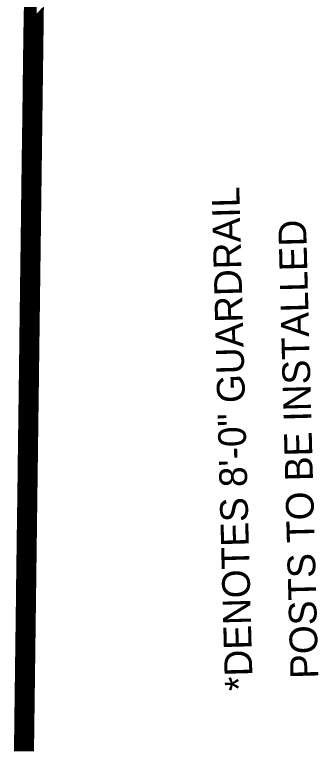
# Model space of a CAD drawing. Extents: x 1929624 to 1936506, y 596315 to 605721.
# Drawn here: x 1932362.2 to 1932427.8, y 600451.3 to 600610.8 of the extents above; entities that cross this region are included whole.
import ezdxf

# ---------------------------------------------------------------- set-up
doc = ezdxf.new("R2010")
doc.units = 0
doc.layers.add('Default', color=7, linetype='Continuous')

msp = doc.modelspace()

# ---------------------------------------------------------------- linework, layer by layer
at = {"layer": 'Default'}
for p, q in [((1932365.29, 600687.8), (1932362.18, 600451.38)), ((1932369.13, 600675.3), (1932366.19, 600451.33)), ((1932365.09, 600672.7), (1932366.76, 600610.75)), ((1932365.08, 600671.45), (1932366.71, 600610.69)), ((1932365.06, 600670.2), (1932366.66, 600610.64)), ((1932365.03, 600667.7), (1932366.56, 600610.54)), ((1932365.04, 600668.95), (1932366.61, 600610.59)), ((1932365.01, 600666.45), (1932366.51, 600610.49)), ((1932364.99, 600665.2), (1932366.46, 600610.43)), ((1932364.98, 600663.95), (1932366.42, 600610.38)), ((1932364.94, 600661.45), (1932366.32, 600610.28)), ((1932364.96, 600662.7), (1932366.37, 600610.33)), ((1932364.93, 600660.19), (1932366.27, 600610.22)), ((1932364.91, 600658.94), (1932366.22, 600610.17)), ((1932364.88, 600656.44), (1932366.12, 600610.07)), ((1932364.9, 600657.69), (1932366.17, 600610.12)), ((1932364.86, 600655.19), (1932366.07, 600610.01)), ((1932364.85, 600653.94), (1932366.03, 600609.96)), ((1932364.83, 600652.69), (1932365.98, 600609.91)), ((1932364.8, 600650.19), (1932365.88, 600609.8)), ((1932364.81, 600651.44), (1932365.93, 600609.86)), ((1932364.78, 600648.93), (1932365.83, 600609.75)), ((1932364.76, 600647.68), (1932365.78, 600609.7)), ((1932364.75, 600646.43), (1932365.73, 600609.65)), ((1932364.71, 600643.93), (1932365.64, 600609.54)), ((1932364.73, 600645.18), (1932365.69, 600609.59)), ((1932364.7, 600642.68), (1932365.59, 600609.49)), ((1932364.68, 600641.43), (1932365.54, 600609.44)), ((1932364.65, 600638.93), (1932365.44, 600609.33)), ((1932364.66, 600640.18), (1932365.49, 600609.39)), ((1932364.63, 600637.68), (1932365.39, 600609.28)), ((1932364.62, 600636.42), (1932365.35, 600609.23)), ((1932364.6, 600635.17), (1932365.3, 600609.18)), ((1932364.57, 600632.67), (1932365.2, 600609.07)), ((1932364.58, 600633.92), (1932365.25, 600609.12)), ((1932364.55, 600631.42), (1932365.15, 600609.02)), ((1932364.53, 600630.17), (1932365.1, 600608.97)), ((1932364.52, 600628.92), (1932365.05, 600608.91)), ((1932364.48, 600626.42), (1932364.96, 600608.81)), ((1932364.5, 600627.67), (1932365.01, 600608.86)), ((1932364.47, 600625.16), (1932364.91, 600608.76)), ((1932364.45, 600623.91), (1932364.86, 600608.7)), ((1932364.42, 600621.41), (1932364.76, 600608.6)), ((1932364.43, 600622.66), (1932364.81, 600608.65)), ((1932364.4, 600620.16), (1932364.71, 600608.55)), ((1932364.39, 600618.91), (1932364.67, 600608.49)), ((1932364.37, 600617.66), (1932364.62, 600608.44)), ((1932364.34, 600615.16), (1932364.52, 600608.34)), ((1932364.35, 600616.41), (1932364.57, 600608.39)), ((1932364.32, 600613.91), (1932364.47, 600608.28)), ((1932364.3, 600612.65), (1932364.42, 600608.23)), ((1932368.12, 600598.45), (1932367.77, 600611.74)), ((1932368.13, 600599.05), (1932367.79, 600611.76)), ((1932368.14, 600599.65), (1932367.81, 600611.79)), ((1932368.15, 600600.25), (1932367.84, 600611.81)), ((1932368.16, 600600.85), (1932367.86, 600611.84)), ((1932368.16, 600601.45), (1932367.88, 600611.86)), ((1932368.17, 600602.05), (1932367.91, 600611.89)), ((1932368.18, 600602.65), (1932367.93, 600611.91)), ((1932368.19, 600603.25), (1932367.95, 600611.93)), ((1932368.19, 600603.85), (1932367.98, 600611.96)), ((1932368.2, 600604.45), (1932368, 600611.98)), ((1932368.21, 600605.05), (1932368.02, 600612.01)), ((1932368.22, 600605.65), (1932368.05, 600612.03)), ((1932368.23, 600606.26), (1932368.07, 600612.06)), ((1932368.23, 600606.86), (1932368.09, 600612.08)), ((1932368.24, 600607.46), (1932368.12, 600612.11)), ((1932368.25, 600608.06), (1932368.14, 600612.13)), ((1932368.26, 600608.66), (1932368.16, 600612.16)), ((1932368.27, 600609.26), (1932368.19, 600612.18)), ((1932368.27, 600609.86), (1932368.21, 600612.21)), ((1932368.28, 600610.46), (1932368.23, 600612.23)), ((1932364.27, 600610.15), (1932364.32, 600608.13)), ((1932364.29, 600611.4), (1932364.37, 600608.18)), ((1932367.61, 600559.42), (1932366.25, 600610.14)), ((1932367.62, 600560.02), (1932366.27, 600610.16)), ((1932367.63, 600560.62), (1932366.3, 600610.19)), ((1932367.63, 600561.22), (1932366.32, 600610.21)), ((1932367.64, 600561.82), (1932366.34, 600610.23)), ((1932367.65, 600562.42), (1932366.37, 600610.26)), ((1932367.66, 600563.02), (1932366.39, 600610.28)), ((1932367.67, 600563.62), (1932366.41, 600610.31)), ((1932367.67, 600564.22), (1932366.44, 600610.33)), ((1932367.68, 600564.82), (1932366.46, 600610.36)), ((1932367.69, 600565.42), (1932366.48, 600610.38)), ((1932367.7, 600566.02), (1932366.51, 600610.41)), ((1932367.71, 600566.62), (1932366.53, 600610.43)), ((1932367.71, 600567.22), (1932366.55, 600610.46)), ((1932367.72, 600567.82), (1932366.58, 600610.48)), ((1932367.73, 600568.42), (1932366.6, 600610.51)), ((1932367.74, 600569.02), (1932366.62, 600610.53)), ((1932367.74, 600569.62), (1932366.65, 600610.55)), ((1932367.75, 600570.22), (1932366.67, 600610.58)), ((1932367.76, 600570.83), (1932366.69, 600610.6)), ((1932367.77, 600571.43), (1932366.72, 600610.63)), ((1932367.78, 600572.03), (1932366.74, 600610.65)), ((1932367.78, 600572.63), (1932366.76, 600610.68)), ((1932367.79, 600573.23), (1932366.79, 600610.7)), ((1932367.8, 600573.83), (1932366.81, 600610.73)), ((1932367.81, 600574.43), (1932366.83, 600610.75)), ((1932367.82, 600575.03), (1932366.86, 600610.78)), ((1932367.82, 600575.63), (1932366.88, 600610.8)), ((1932367.83, 600576.23), (1932366.9, 600610.83)), ((1932367.84, 600576.83), (1932366.93, 600610.85)), ((1932367.85, 600577.43), (1932366.95, 600610.88)), ((1932367.86, 600578.03), (1932366.97, 600610.9)), ((1932367.86, 600578.63), (1932367, 600610.92)), ((1932367.87, 600579.23), (1932367.02, 600610.95)), ((1932367.88, 600579.83), (1932367.04, 600610.97)), ((1932367.89, 600580.43), (1932367.07, 600611)), ((1932367.89, 600581.03), (1932367.09, 600611.02)), ((1932367.9, 600581.64), (1932367.11, 600611.05)), ((1932367.91, 600582.24), (1932367.14, 600611.07)), ((1932367.92, 600582.84), (1932367.16, 600611.1)), ((1932367.93, 600583.44), (1932367.18, 600611.12)), ((1932367.93, 600584.04), (1932367.21, 600611.15)), ((1932367.94, 600584.64), (1932367.23, 600611.17)), ((1932367.95, 600585.24), (1932367.25, 600611.2)), ((1932367.96, 600585.84), (1932367.28, 600611.22)), ((1932367.97, 600586.44), (1932367.3, 600611.24)), ((1932367.97, 600587.04), (1932367.32, 600611.27)), ((1932367.98, 600587.64), (1932367.35, 600611.29)), ((1932367.99, 600588.24), (1932367.37, 600611.32)), ((1932368, 600588.84), (1932367.39, 600611.34)), ((1932368.01, 600589.44), (1932367.42, 600611.37)), ((1932368.01, 600590.04), (1932367.44, 600611.39)), ((1932368.02, 600590.64), (1932367.46, 600611.42)), ((1932368.03, 600591.24), (1932367.49, 600611.44)), ((1932368.04, 600591.84), (1932367.51, 600611.47)), ((1932368.04, 600592.45), (1932367.53, 600611.49)), ((1932368.05, 600593.05), (1932367.56, 600611.52)), ((1932368.06, 600593.65), (1932367.58, 600611.54)), ((1932368.07, 600594.25), (1932367.6, 600611.56)), ((1932368.08, 600594.85), (1932367.63, 600611.59)), ((1932368.08, 600595.45), (1932367.65, 600611.61)), ((1932368.09, 600596.05), (1932367.67, 600611.64)), ((1932368.1, 600596.65), (1932367.7, 600611.66)), ((1932368.11, 600597.25), (1932367.72, 600611.69)), ((1932368.12, 600597.85), (1932367.74, 600611.71)), ((1932364.25, 600608.9), (1932364.28, 600608.08)), ((1932367.11, 600520.98), (1932364.76, 600608.56)), ((1932367.11, 600521.59), (1932364.78, 600608.58)), ((1932367.12, 600522.19), (1932364.8, 600608.61)), ((1932367.13, 600522.79), (1932364.83, 600608.63)), ((1932367.14, 600523.39), (1932364.85, 600608.66)), ((1932367.15, 600523.99), (1932364.87, 600608.68)), ((1932367.15, 600524.59), (1932364.9, 600608.71)), ((1932367.16, 600525.19), (1932364.92, 600608.73)), ((1932367.17, 600525.79), (1932364.94, 600608.76)), ((1932367.18, 600526.39), (1932364.97, 600608.78)), ((1932367.18, 600526.99), (1932364.99, 600608.81)), ((1932367.19, 600527.59), (1932365.01, 600608.83)), ((1932367.2, 600528.19), (1932365.04, 600608.86)), ((1932367.21, 600528.79), (1932365.06, 600608.88)), ((1932367.22, 600529.39), (1932365.08, 600608.9)), ((1932367.22, 600529.99), (1932365.11, 600608.93)), ((1932367.23, 600530.59), (1932365.13, 600608.95)), ((1932367.24, 600531.19), (1932365.15, 600608.98)), ((1932367.25, 600531.79), (1932365.18, 600609)), ((1932367.26, 600532.39), (1932365.2, 600609.03)), ((1932367.26, 600532.99), (1932365.22, 600609.05)), ((1932367.27, 600533.59), (1932365.25, 600609.08)), ((1932367.28, 600534.19), (1932365.27, 600609.1)), ((1932367.29, 600534.79), (1932365.29, 600609.13)), ((1932367.3, 600535.4), (1932365.32, 600609.15)), ((1932367.3, 600536), (1932365.34, 600609.18)), ((1932367.31, 600536.6), (1932365.36, 600609.2)), ((1932367.32, 600537.2), (1932365.39, 600609.22)), ((1932367.33, 600537.8), (1932365.41, 600609.25)), ((1932367.33, 600538.4), (1932365.43, 600609.27)), ((1932367.34, 600539), (1932365.46, 600609.3)), ((1932367.35, 600539.6), (1932365.48, 600609.32)), ((1932367.36, 600540.2), (1932365.5, 600609.35)), ((1932367.37, 600540.8), (1932365.53, 600609.37)), ((1932367.37, 600541.4), (1932365.55, 600609.4)), ((1932367.38, 600542), (1932365.57, 600609.42)), ((1932367.39, 600542.6), (1932365.6, 600609.45)), ((1932367.4, 600543.2), (1932365.62, 600609.47)), ((1932367.41, 600543.8), (1932365.64, 600609.5)), ((1932367.41, 600544.4), (1932365.67, 600609.52)), ((1932367.42, 600545), (1932365.69, 600609.54)), ((1932367.43, 600545.6), (1932365.71, 600609.57)), ((1932367.44, 600546.21), (1932365.74, 600609.59)), ((1932367.45, 600546.81), (1932365.76, 600609.62)), ((1932367.45, 600547.41), (1932365.78, 600609.64)), ((1932367.46, 600548.01), (1932365.81, 600609.67)), ((1932367.47, 600548.61), (1932365.83, 600609.69)), ((1932367.48, 600549.21), (1932365.85, 600609.72)), ((1932367.48, 600549.81), (1932365.88, 600609.74)), ((1932367.49, 600550.41), (1932365.9, 600609.77)), ((1932367.5, 600551.01), (1932365.92, 600609.79)), ((1932367.51, 600551.61), (1932365.95, 600609.82)), ((1932367.52, 600552.21), (1932365.97, 600609.84)), ((1932367.52, 600552.81), (1932365.99, 600609.87)), ((1932367.53, 600553.41), (1932366.02, 600609.89)), ((1932367.54, 600554.01), (1932366.04, 600609.91)), ((1932367.55, 600554.61), (1932366.06, 600609.94)), ((1932367.56, 600555.21), (1932366.09, 600609.96)), ((1932367.56, 600555.81), (1932366.11, 600609.99)), ((1932367.57, 600556.41), (1932366.13, 600610.01)), ((1932367.58, 600557.02), (1932366.16, 600610.04)), ((1932367.59, 600557.62), (1932366.18, 600610.06)), ((1932367.59, 600558.22), (1932366.2, 600610.09)), ((1932367.6, 600558.82), (1932366.23, 600610.11)), ((1932366.92, 600507.17), (1932364.23, 600607.39)), ((1932366.93, 600507.77), (1932364.24, 600607.99)), ((1932366.94, 600508.37), (1932364.26, 600608.04)), ((1932366.95, 600508.97), (1932364.29, 600608.07)), ((1932366.96, 600509.57), (1932364.31, 600608.09)), ((1932366.96, 600510.17), (1932364.33, 600608.12)), ((1932366.97, 600510.78), (1932364.36, 600608.14)), ((1932366.98, 600511.38), (1932364.38, 600608.17)), ((1932366.99, 600511.98), (1932364.4, 600608.19)), ((1932367, 600512.58), (1932364.43, 600608.21)), ((1932367, 600513.18), (1932364.45, 600608.24)), ((1932367.01, 600513.78), (1932364.47, 600608.26)), ((1932367.02, 600514.38), (1932364.5, 600608.29)), ((1932367.03, 600514.98), (1932364.52, 600608.31)), ((1932367.03, 600515.58), (1932364.54, 600608.34)), ((1932367.04, 600516.18), (1932364.57, 600608.36)), ((1932367.05, 600516.78), (1932364.59, 600608.39)), ((1932367.06, 600517.38), (1932364.61, 600608.41)), ((1932367.07, 600517.98), (1932364.64, 600608.44)), ((1932367.07, 600518.58), (1932364.66, 600608.46)), ((1932367.08, 600519.18), (1932364.68, 600608.49)), ((1932367.09, 600519.78), (1932364.71, 600608.51)), ((1932367.1, 600520.38), (1932364.73, 600608.53)), ((1932366.9, 600505.37), (1932364.21, 600605.59)), ((1932366.91, 600505.97), (1932364.22, 600606.19)), ((1932366.92, 600506.57), (1932364.23, 600606.79)), ((1932366.89, 600504.17), (1932364.19, 600604.39)), ((1932366.88, 600503.57), (1932364.19, 600603.79)), ((1932366.89, 600504.77), (1932364.2, 600604.99)), ((1932366.86, 600502.37), (1932364.17, 600602.59)), ((1932366.87, 600502.97), (1932364.18, 600603.19)), ((1932366.84, 600500.57), (1932364.15, 600600.78)), ((1932366.85, 600501.77), (1932364.16, 600601.99)), ((1932366.85, 600501.17), (1932364.16, 600601.39)), ((1932366.81, 600498.77), (1932364.12, 600598.98)), ((1932366.82, 600499.37), (1932364.13, 600599.58)), ((1932366.83, 600499.97), (1932364.14, 600600.18)), ((1932366.8, 600497.56), (1932364.11, 600597.78)), ((1932366.81, 600498.17), (1932364.12, 600598.38)), ((1932366.77, 600495.76), (1932364.08, 600595.98)), ((1932366.78, 600496.36), (1932364.09, 600596.58)), ((1932366.79, 600496.96), (1932364.1, 600597.18)), ((1932366.76, 600494.56), (1932364.07, 600594.78)), ((1932366.77, 600495.16), (1932364.08, 600595.38)), ((1932366.74, 600492.76), (1932364.04, 600592.98)), ((1932366.74, 600493.36), (1932364.05, 600593.58)), ((1932366.75, 600493.96), (1932364.06, 600594.18)), ((1932366.71, 600490.96), (1932364.02, 600591.18)), ((1932366.72, 600491.56), (1932364.03, 600591.78)), ((1932366.73, 600492.16), (1932364.04, 600592.38)), ((1932366.7, 600490.36), (1932364.01, 600590.57)), ((1932366.7, 600489.76), (1932364.01, 600589.97)), ((1932366.67, 600487.96), (1932363.98, 600588.17)), ((1932366.68, 600488.56), (1932363.99, 600588.77)), ((1932366.69, 600489.16), (1932364, 600589.37)), ((1932366.65, 600486.16), (1932363.96, 600586.37)), ((1932366.66, 600487.36), (1932363.97, 600587.57)), ((1932366.66, 600486.76), (1932363.97, 600586.97)), ((1932366.63, 600484.95), (1932363.94, 600585.17)), ((1932366.64, 600485.55), (1932363.95, 600585.77)), ((1932366.61, 600483.15), (1932363.92, 600583.37)), ((1932366.62, 600484.35), (1932363.93, 600584.57)), ((1932366.62, 600483.75), (1932363.93, 600583.97)), ((1932366.59, 600481.35), (1932363.89, 600581.57)), ((1932366.59, 600481.95), (1932363.9, 600582.17)), ((1932366.6, 600482.55), (1932363.91, 600582.77)), ((1932366.57, 600480.15), (1932363.88, 600580.37)), ((1932366.58, 600480.75), (1932363.89, 600580.97)), ((1932366.55, 600478.95), (1932363.86, 600579.17)), ((1932366.55, 600478.35), (1932363.86, 600578.57)), ((1932366.56, 600479.55), (1932363.87, 600579.77)), ((1932366.52, 600476.55), (1932363.83, 600576.77)), ((1932366.53, 600477.15), (1932363.84, 600577.37)), ((1932366.54, 600477.75), (1932363.85, 600577.97)), ((1932366.51, 600475.95), (1932363.82, 600576.16)), ((1932366.51, 600475.35), (1932363.82, 600575.56)), ((1932366.48, 600473.54), (1932363.79, 600573.76)), ((1932366.49, 600474.14), (1932363.8, 600574.36)), ((1932366.5, 600474.74), (1932363.81, 600574.96)), ((1932366.46, 600471.74), (1932363.77, 600571.96)), ((1932366.47, 600472.94), (1932363.78, 600573.16)), ((1932366.47, 600472.34), (1932363.78, 600572.56)), ((1932366.44, 600470.54), (1932363.75, 600570.76)), ((1932366.45, 600471.14), (1932363.76, 600571.36)), ((1932366.42, 600468.74), (1932363.73, 600568.96)), ((1932366.43, 600469.34), (1932363.74, 600569.56)), ((1932366.44, 600469.94), (1932363.75, 600570.16)), ((1932366.4, 600467.54), (1932363.71, 600567.76)), ((1932366.4, 600466.94), (1932363.71, 600567.16)), ((1932366.41, 600468.14), (1932363.72, 600568.36)), ((1932366.38, 600465.74), (1932363.69, 600565.95)), ((1932366.39, 600466.34), (1932363.7, 600566.56)), ((1932366.36, 600464.54), (1932363.67, 600564.75)), ((1932366.36, 600463.94), (1932363.67, 600564.15)), ((1932366.37, 600465.14), (1932363.68, 600565.35)), ((1932366.33, 600462.14), (1932363.64, 600562.35)), ((1932366.34, 600462.74), (1932363.65, 600562.95)), ((1932366.35, 600463.34), (1932363.66, 600563.55)), ((1932366.32, 600461.54), (1932363.63, 600561.75)), ((1932366.32, 600460.93), (1932363.63, 600561.15)), ((1932366.29, 600459.13), (1932363.6, 600559.35)), ((1932366.3, 600459.73), (1932363.61, 600559.95)), ((1932366.31, 600460.33), (1932363.62, 600560.55)), ((1932366.27, 600457.33), (1932363.58, 600557.55)), ((1932366.28, 600457.93), (1932363.59, 600558.15)), ((1932366.29, 600458.53), (1932363.6, 600558.75)), ((1932366.25, 600456.13), (1932363.56, 600556.35)), ((1932366.26, 600456.73), (1932363.57, 600556.95)), ((1932366.23, 600454.33), (1932363.54, 600554.55)), ((1932366.24, 600454.93), (1932363.55, 600555.15)), ((1932366.25, 600455.53), (1932363.56, 600555.75)), ((1932366.21, 600453.13), (1932363.52, 600553.34)), ((1932366.21, 600452.53), (1932363.52, 600552.74)), ((1932366.22, 600453.73), (1932363.53, 600553.94)), ((1932366.19, 600451.33), (1932363.5, 600551.54)), ((1932366.2, 600451.93), (1932363.51, 600552.14)), ((1932366.14, 600451.33), (1932363.48, 600550.34)), ((1932366.12, 600451.33), (1932363.48, 600549.74)), ((1932366.17, 600451.32), (1932363.49, 600550.94)), ((1932366.07, 600451.33), (1932363.46, 600548.54)), ((1932366.09, 600451.33), (1932363.47, 600549.14)), ((1932366, 600451.33), (1932363.44, 600546.74)), ((1932366.05, 600451.33), (1932363.45, 600547.94)), ((1932366.02, 600451.33), (1932363.45, 600547.34)), ((1932365.93, 600451.33), (1932363.41, 600544.94)), ((1932365.95, 600451.33), (1932363.42, 600545.54)), ((1932365.97, 600451.33), (1932363.43, 600546.14)), ((1932365.88, 600451.33), (1932363.4, 600543.74)), ((1932365.9, 600451.33), (1932363.41, 600544.34)), ((1932365.81, 600451.33), (1932363.37, 600541.94)), ((1932365.83, 600451.33), (1932363.38, 600542.54)), ((1932365.85, 600451.33), (1932363.39, 600543.14)), ((1932365.73, 600451.33), (1932363.35, 600540.13)), ((1932365.76, 600451.33), (1932363.36, 600540.73)), ((1932365.78, 600451.33), (1932363.37, 600541.34)), ((1932365.69, 600451.33), (1932363.33, 600538.93)), ((1932365.71, 600451.33), (1932363.34, 600539.53)), ((1932365.61, 600451.33), (1932363.31, 600537.13)), ((1932365.64, 600451.33), (1932363.32, 600537.73)), ((1932365.66, 600451.33), (1932363.33, 600538.33)), ((1932365.54, 600451.33), (1932363.29, 600535.33)), ((1932365.59, 600451.33), (1932363.3, 600536.53)), ((1932365.57, 600451.33), (1932363.3, 600535.93)), ((1932365.49, 600451.34), (1932363.27, 600534.13)), ((1932365.52, 600451.33), (1932363.28, 600534.73)), ((1932365.42, 600451.34), (1932363.25, 600532.33)), ((1932365.47, 600451.34), (1932363.26, 600533.53)), ((1932365.45, 600451.33), (1932363.26, 600532.93)), ((1932365.35, 600451.34), (1932363.22, 600530.52)), ((1932365.37, 600451.34), (1932363.23, 600531.13)), ((1932365.4, 600451.34), (1932363.24, 600531.73)), ((1932365.3, 600451.34), (1932363.21, 600529.32)), ((1932365.33, 600451.34), (1932363.22, 600529.92)), ((1932365.25, 600451.34), (1932363.19, 600528.12)), ((1932365.23, 600451.34), (1932363.19, 600527.52)), ((1932365.28, 600451.34), (1932363.2, 600528.72)), ((1932365.16, 600451.34), (1932363.16, 600525.72)), ((1932365.18, 600451.34), (1932363.17, 600526.32)), ((1932365.21, 600451.34), (1932363.18, 600526.92)), ((1932365.13, 600451.34), (1932363.15, 600525.12)), ((1932365.11, 600451.34), (1932363.15, 600524.52)), ((1932365.04, 600451.34), (1932363.12, 600522.72)), ((1932365.06, 600451.34), (1932363.13, 600523.32)), ((1932365.09, 600451.34), (1932363.14, 600523.92)), ((1932364.97, 600451.34), (1932363.1, 600520.92)), ((1932365.01, 600451.34), (1932363.11, 600522.12)), ((1932364.99, 600451.34), (1932363.11, 600521.52)), ((1932364.92, 600451.34), (1932363.08, 600519.72)), ((1932364.94, 600451.34), (1932363.09, 600520.32)), ((1932364.85, 600451.34), (1932363.06, 600517.92)), ((1932364.89, 600451.34), (1932363.07, 600519.12)), ((1932364.87, 600451.34), (1932363.07, 600518.52)), ((1932364.8, 600451.34), (1932363.04, 600516.72)), ((1932364.77, 600451.35), (1932363.04, 600516.11)), ((1932364.82, 600451.34), (1932363.05, 600517.32)), ((1932364.73, 600451.35), (1932363.02, 600514.91)), ((1932364.75, 600451.34), (1932363.03, 600515.51)), ((1932364.68, 600451.35), (1932363, 600513.71)), ((1932364.65, 600451.35), (1932363, 600513.11)), ((1932364.7, 600451.35), (1932363.01, 600514.31)), ((1932364.58, 600451.35), (1932362.97, 600511.31)), ((1932364.61, 600451.35), (1932362.98, 600511.91)), ((1932364.63, 600451.35), (1932362.99, 600512.51)), ((1932364.56, 600451.35), (1932362.96, 600510.71)), ((1932364.53, 600451.35), (1932362.96, 600510.11)), ((1932364.46, 600451.35), (1932362.93, 600508.31)), ((1932364.49, 600451.35), (1932362.94, 600508.91)), ((1932364.51, 600451.35), (1932362.95, 600509.51)), ((1932364.39, 600451.35), (1932362.91, 600506.51)), ((1932364.44, 600451.35), (1932362.92, 600507.71)), ((1932364.41, 600451.35), (1932362.92, 600507.11)), ((1932364.34, 600451.35), (1932362.89, 600505.3)), ((1932364.37, 600451.35), (1932362.9, 600505.91)), ((1932364.27, 600451.35), (1932362.87, 600503.5)), ((1932364.29, 600451.35), (1932362.88, 600504.1)), ((1932364.32, 600451.35), (1932362.89, 600504.7)), ((1932364.22, 600451.35), (1932362.85, 600502.3)), ((1932364.2, 600451.35), (1932362.85, 600501.7)), ((1932364.25, 600451.35), (1932362.86, 600502.9)), ((1932364.15, 600451.35), (1932362.83, 600500.5)), ((1932364.17, 600451.35), (1932362.84, 600501.1)), ((1932364.1, 600451.35), (1932362.81, 600499.3)), ((1932364.08, 600451.35), (1932362.81, 600498.7)), ((1932364.13, 600451.35), (1932362.82, 600499.9)), ((1932364.03, 600451.35), (1932362.79, 600497.5)), ((1932364.05, 600451.35), (1932362.8, 600498.1)), ((1932363.98, 600451.36), (1932362.77, 600496.3)), ((1932363.96, 600451.35), (1932362.77, 600495.7)), ((1932364.01, 600451.36), (1932362.78, 600496.9)), ((1932363.89, 600451.36), (1932362.74, 600493.89)), ((1932363.91, 600451.36), (1932362.75, 600494.49)), ((1932363.93, 600451.36), (1932362.76, 600495.09)), ((1932363.84, 600451.36), (1932362.73, 600492.69)), ((1932363.86, 600451.36), (1932362.74, 600493.29)), ((1932363.77, 600451.36), (1932362.7, 600490.89)), ((1932363.79, 600451.36), (1932362.71, 600491.49)), ((1932363.81, 600451.36), (1932362.72, 600492.09)), ((1932363.69, 600451.36), (1932362.68, 600489.09)), ((1932363.72, 600451.36), (1932362.69, 600489.69)), ((1932363.74, 600451.36), (1932362.7, 600490.29)), ((1932363.64, 600451.36), (1932362.66, 600487.89)), ((1932363.67, 600451.36), (1932362.67, 600488.49)), ((1932363.57, 600451.36), (1932362.64, 600486.09)), ((1932363.6, 600451.36), (1932362.65, 600486.69)), ((1932363.62, 600451.36), (1932362.66, 600487.29)), ((1932363.52, 600451.36), (1932362.62, 600484.89)), ((1932363.5, 600451.36), (1932362.62, 600484.29)), ((1932363.55, 600451.36), (1932362.63, 600485.49)), ((1932363.45, 600451.36), (1932362.6, 600483.09)), ((1932363.48, 600451.36), (1932362.61, 600483.69)), ((1932363.38, 600451.36), (1932362.58, 600481.29)), ((1932363.43, 600451.36), (1932362.59, 600482.49)), ((1932363.4, 600451.36), (1932362.59, 600481.89)), ((1932363.31, 600451.36), (1932362.55, 600479.48)), ((1932363.33, 600451.36), (1932362.56, 600480.08)), ((1932363.36, 600451.36), (1932362.57, 600480.68)), ((1932363.26, 600451.36), (1932362.54, 600478.28)), ((1932363.28, 600451.37), (1932362.55, 600478.88)), ((1932363.19, 600451.37), (1932362.51, 600476.48)), ((1932363.21, 600451.37), (1932362.52, 600477.08)), ((1932363.24, 600451.36), (1932362.53, 600477.68)), ((1932363.12, 600451.37), (1932362.49, 600474.68)), ((1932363.14, 600451.37), (1932362.5, 600475.28)), ((1932363.16, 600451.37), (1932362.51, 600475.88)), ((1932363.09, 600451.37), (1932362.48, 600474.08)), ((1932363.07, 600451.37), (1932362.48, 600473.48)), ((1932363, 600451.37), (1932362.45, 600471.68)), ((1932363.02, 600451.37), (1932362.46, 600472.28)), ((1932363.04, 600451.37), (1932362.47, 600472.88)), ((1932362.92, 600451.37), (1932362.43, 600469.87)), ((1932362.97, 600451.37), (1932362.44, 600471.08)), ((1932362.95, 600451.37), (1932362.44, 600470.47)), ((1932362.88, 600451.37), (1932362.41, 600468.67)), ((1932362.9, 600451.37), (1932362.42, 600469.27)), ((1932362.8, 600451.37), (1932362.39, 600466.87)), ((1932362.85, 600451.37), (1932362.4, 600468.07)), ((1932362.83, 600451.37), (1932362.4, 600467.47)), ((1932362.73, 600451.37), (1932362.36, 600465.07)), ((1932362.76, 600451.37), (1932362.37, 600465.67)), ((1932362.78, 600451.37), (1932362.38, 600466.27)), ((1932362.68, 600451.37), (1932362.35, 600463.87)), ((1932362.71, 600451.37), (1932362.36, 600464.47)), ((1932362.64, 600451.37), (1932362.33, 600462.67)), ((1932362.61, 600451.37), (1932362.33, 600462.07)), ((1932362.66, 600451.37), (1932362.34, 600463.27)), ((1932362.54, 600451.37), (1932362.3, 600460.27)), ((1932362.56, 600451.37), (1932362.31, 600460.87)), ((1932362.59, 600451.37), (1932362.32, 600461.47)), ((1932362.52, 600451.37), (1932362.29, 600459.66)), ((1932362.49, 600451.38), (1932362.29, 600459.06)), ((1932362.42, 600451.38), (1932362.26, 600457.26)), ((1932362.44, 600451.38), (1932362.27, 600457.86)), ((1932362.47, 600451.37), (1932362.28, 600458.46)), ((1932362.35, 600451.38), (1932362.24, 600455.46)), ((1932362.4, 600451.38), (1932362.25, 600456.66)), ((1932362.37, 600451.38), (1932362.25, 600456.06)), ((1932362.3, 600451.38), (1932362.22, 600454.26)), ((1932362.32, 600451.38), (1932362.23, 600454.86)), ((1932362.23, 600451.38), (1932362.2, 600452.46)), ((1932362.28, 600451.38), (1932362.21, 600453.66)), ((1932362.25, 600451.38), (1932362.21, 600453.06)), ((1932362.2, 600451.38), (1932362.19, 600451.86))]:
    msp.add_line(p, q, dxfattribs=at)

# ---------------------------------------------------------------- texts
for s, p in [('*DENOTES 8\'-0" GUARDRAIL', (1932413.64, 600464.48)), (' POSTS TO BE INSTALLED', (1932427.87, 600464.86))]:
    msp.add_text(s, height=6, rotation=91.5377, dxfattribs=at).set_placement(p)

doc.saveas('drawing.dxf')
